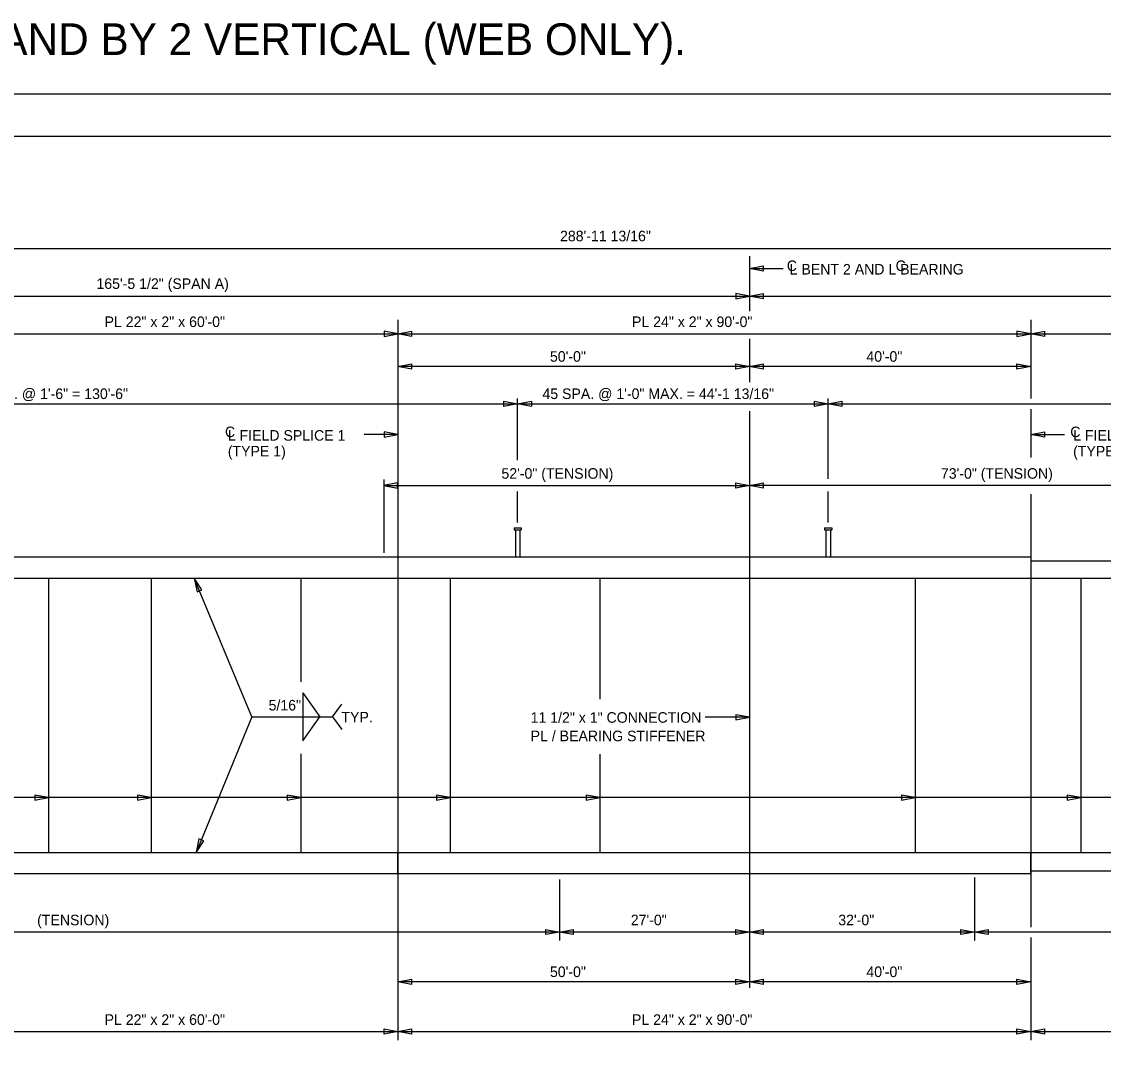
# Model space of a CAD drawing. Extents: x -383 to 7, y -330 to -94.
# Drawn here: x -255.6 to -204.4, y -145.2 to -96.1 of the extents above; entities that cross this region are included whole.
import ezdxf

# ---------------------------------------------------------------- set-up
doc = ezdxf.new("R2010")
doc.units = 0
for name, color, linetype in [('BR_AUTO DIMENSION', 7, 'Continuous'), ('BR_BORDER LINES', 7, 'Continuous'), ('BR_CENTER LINES', 7, 'Continuous'), ('BR_STRUCTURAL STEEL', 7, 'Continuous'), ('BR_TEXT', 7, 'Continuous'), ('Default', 7, 'Continuous'), ('Level 31', 7, 'Continuous')]:
    doc.layers.add(name, color=color, linetype=linetype)

msp = doc.modelspace()

# ---------------------------------------------------------------- linework, layer by layer
at = {"layer": 'BR_AUTO DIMENSION'}
for p, q in [((-276.288, -106.806), (-179.96, -106.806)), ((-221.135, -107.745), (-219.537, -107.745)), ((-276.288, -109.064), (-221.135, -109.064)), ((-221.135, -109.064), (-179.96, -109.064)), ((-257.802, -110.841), (-237.802, -110.841)), ((-237.802, -110.841), (-207.802, -110.841)), ((-207.802, -110.841), (-179.96, -110.841)), ((-221.135, -112.391), (-237.802, -112.391)), ((-207.802, -112.391), (-221.135, -112.391)), ((-274.622, -114.159), (-232.122, -114.159)), ((-232.122, -116.833), (-232.122, -113.909)), ((-232.122, -114.159), (-217.404, -114.159)), ((-217.404, -117.713), (-217.404, -113.909)), ((-217.404, -114.159), (-181.155, -114.159)), ((-237.802, -115.615), (-239.401, -115.615)), ((-207.802, -115.615), (-206.203, -115.615)), ((-238.469, -117.738), (-238.469, -121.213)), ((-238.469, -118.028), (-221.135, -118.028)), ((-232.122, -119.787), (-232.122, -118.317)), ((-196.802, -118.028), (-221.135, -118.028)), ((-217.404, -119.787), (-217.404, -118.317)), ((-244.714, -128.987), (-247.452, -122.412)), ((-242.299, -127.854), (-242.299, -130.121)), ((-242.299, -127.854), (-241.493, -128.987)), ((-240.89, -128.987), (-240.457, -128.38)), ((-244.714, -128.987), (-247.363, -135.412)), ((-244.714, -128.987), (-240.89, -128.987)), ((-242.299, -130.121), (-241.493, -128.987)), ((-240.89, -128.987), (-240.457, -129.595)), ((-221.135, -129.011), (-223.237, -129.011)), ((-185.75, -132.816), (-283.86, -132.816)), ((-230.135, -136.687), (-230.135, -139.586)), ((-210.469, -136.592), (-210.469, -139.586)), ((-230.135, -139.18), (-276.288, -139.18)), ((-221.135, -139.18), (-230.135, -139.18)), ((-210.469, -139.18), (-221.135, -139.18)), ((-179.96, -139.18), (-210.469, -139.18)), ((-221.135, -141.539), (-237.802, -141.539)), ((-207.802, -141.539), (-221.135, -141.539)), ((-257.802, -143.898), (-237.802, -143.898)), ((-237.802, -143.898), (-207.802, -143.898)), ((-207.802, -143.898), (-179.96, -143.898))]:
    msp.add_line(p, q, dxfattribs=at)
for points in [[(-220.485, -107.87), (-221.135, -107.745), (-220.485, -107.62)], [(-221.785, -109.189), (-221.135, -109.064), (-221.785, -108.939)], [(-220.485, -109.189), (-221.135, -109.064), (-220.485, -108.939)], [(-238.452, -110.966), (-237.802, -110.841), (-238.452, -110.716)], [(-237.152, -110.966), (-237.802, -110.841), (-237.152, -110.716)], [(-208.452, -110.966), (-207.802, -110.841), (-208.452, -110.716)], [(-207.152, -110.966), (-207.802, -110.841), (-207.152, -110.716)], [(-237.152, -112.516), (-237.802, -112.391), (-237.152, -112.266)], [(-221.785, -112.266), (-221.135, -112.391), (-221.785, -112.516)], [(-220.485, -112.516), (-221.135, -112.391), (-220.485, -112.266)], [(-208.452, -112.266), (-207.802, -112.391), (-208.452, -112.516)], [(-232.772, -114.034), (-232.122, -114.159), (-232.772, -114.284)], [(-231.472, -114.284), (-232.122, -114.159), (-231.472, -114.034)], [(-218.054, -114.034), (-217.404, -114.159), (-218.054, -114.284)], [(-216.754, -114.284), (-217.404, -114.159), (-216.754, -114.034)], [(-238.452, -115.74), (-237.802, -115.615), (-238.452, -115.49)], [(-207.152, -115.74), (-207.802, -115.615), (-207.152, -115.49)], [(-237.819, -117.903), (-238.469, -118.028), (-237.819, -118.153)], [(-221.785, -117.903), (-221.135, -118.028), (-221.785, -118.153)], [(-220.485, -118.153), (-221.135, -118.028), (-220.485, -117.903)], [(-247.087, -122.964), (-247.452, -122.412), (-247.317, -123.061)], [(-221.785, -129.136), (-221.135, -129.011), (-221.785, -128.886)], [(-255.007, -132.941), (-254.357, -132.816), (-255.007, -132.691)], [(-250.141, -132.941), (-249.491, -132.816), (-250.141, -132.691)], [(-243.052, -132.941), (-242.402, -132.816), (-243.052, -132.691)], [(-235.963, -132.941), (-235.313, -132.816), (-235.963, -132.691)], [(-228.874, -132.941), (-228.224, -132.816), (-228.874, -132.691)], [(-213.929, -132.941), (-213.279, -132.816), (-213.929, -132.691)], [(-206.072, -132.941), (-205.422, -132.816), (-206.072, -132.691)], [(-247.231, -134.764), (-247.363, -135.412), (-247, -134.859)], [(-230.785, -139.055), (-230.135, -139.18), (-230.785, -139.305)], [(-229.485, -139.305), (-230.135, -139.18), (-229.485, -139.055)], [(-221.785, -139.055), (-221.135, -139.18), (-221.785, -139.305)], [(-220.485, -139.305), (-221.135, -139.18), (-220.485, -139.055)], [(-211.119, -139.055), (-210.469, -139.18), (-211.119, -139.305)], [(-209.819, -139.305), (-210.469, -139.18), (-209.819, -139.055)], [(-237.152, -141.664), (-237.802, -141.539), (-237.152, -141.414)], [(-221.785, -141.414), (-221.135, -141.539), (-221.785, -141.664)], [(-220.485, -141.664), (-221.135, -141.539), (-220.485, -141.414)], [(-208.452, -141.414), (-207.802, -141.539), (-208.452, -141.664)], [(-238.452, -143.773), (-237.802, -143.898), (-238.452, -144.023)], [(-237.152, -144.023), (-237.802, -143.898), (-237.152, -143.773)], [(-208.452, -143.773), (-207.802, -143.898), (-208.452, -144.023)], [(-207.152, -144.023), (-207.802, -143.898), (-207.152, -143.773)]]:
    msp.add_lwpolyline(points, close=True, dxfattribs=at)
at = {"layer": 'BR_BORDER LINES'}
msp.add_line((-163.178, -101.489), (-297.843, -101.489), dxfattribs=at)
at = {"layer": 'BR_CENTER LINES'}
for p, q in [((-221.135, -107.17), (-221.135, -109.769)), ((-237.802, -110.184), (-237.802, -144.298)), ((-207.802, -110.184), (-207.802, -113.912)), ((-221.135, -111.078), (-221.135, -113.133)), ((-221.135, -114.504), (-221.135, -122.412)), ((-207.802, -114.419), (-207.802, -116.7)), ((-207.802, -118.447), (-207.802, -138.953)), ((-221.135, -135.412), (-221.135, -141.826)), ((-207.802, -139.444), (-207.802, -144.298))]:
    msp.add_line(p, q, dxfattribs=at)
at = {"layer": 'BR_STRUCTURAL STEEL'}
for p, q in [((-257.802, -121.412), (-237.802, -121.412)), ((-237.802, -121.412), (-237.802, -122.412)), ((-237.802, -121.412), (-207.802, -121.412)), ((-207.802, -121.412), (-207.802, -122.412)), ((-207.802, -121.6), (-179.96, -121.6)), ((-276.288, -122.412), (-179.96, -122.412)), ((-254.357, -122.412), (-254.357, -135.412)), ((-249.491, -122.412), (-249.491, -135.412)), ((-242.402, -122.412), (-242.402, -127.337)), ((-235.313, -122.412), (-235.313, -135.412)), ((-228.224, -122.412), (-228.224, -128.158)), ((-221.135, -122.412), (-221.135, -135.412)), ((-213.279, -122.412), (-213.279, -135.412)), ((-205.422, -122.412), (-205.422, -135.412)), ((-242.402, -130.739), (-242.402, -135.412)), ((-228.224, -130.754), (-228.224, -135.412)), ((-276.288, -135.412), (-179.96, -135.412)), ((-237.802, -136.412), (-237.802, -135.412)), ((-207.802, -136.412), (-207.802, -135.412)), ((-207.802, -136.287), (-179.96, -136.287)), ((-257.802, -136.412), (-237.802, -136.412)), ((-237.802, -136.412), (-207.802, -136.412))]:
    msp.add_line(p, q, dxfattribs=at)
at = {"layer": 'Default'}
for p, q in [((-232.294, -120.037), (-232.294, -120.131)), ((-232.294, -120.037), (-231.95, -120.037)), ((-232.294, -120.131), (-231.95, -120.131)), ((-232.231, -120.131), (-232.231, -121.412)), ((-232.012, -120.131), (-232.012, -121.412)), ((-231.95, -120.037), (-231.95, -120.131)), ((-217.576, -120.037), (-217.576, -120.131)), ((-217.576, -120.037), (-217.233, -120.037)), ((-217.576, -120.131), (-217.233, -120.131)), ((-217.514, -120.131), (-217.514, -121.412)), ((-217.295, -120.131), (-217.295, -121.412)), ((-217.233, -120.037), (-217.233, -120.131))]:
    msp.add_line(p, q, dxfattribs=at)
at = {"layer": 'Level 31'}
msp.add_lwpolyline([(-305.176, -187.489), (-161.176, -187.489), (-161.176, -99.489), (-305.176, -99.489)], close=True, dxfattribs=at)

# ---------------------------------------------------------------- texts
at = {"layer": 'BR_AUTO DIMENSION'}
for s, p in [('288\'-11 13/16"', (-230.112, -106.46)), ('165\'-5 1/2" (SPAN A)', (-252.087, -108.717)), ('PL 22" x 2" x 60\'-0"', (-251.701, -110.522)), ('PL 24" x 2" x 90\'-0"', (-226.701, -110.522)), ('50\'-0"', (-230.59, -112.166)), ('40\'-0"', (-215.59, -112.166)), ('87 SPA. @ 1\'-6" = 130\'-6"', (-258.263, -113.933)), ('45 SPA. @ 1\'-0" MAX. = 44\'-1 13/16"', (-230.946, -113.933)), (' 73\'-0" (TENSION)', (-212.243, -117.708)), ('5/16"', (-243.927, -128.687)), ('TYP.', (-240.473, -129.254)), ('(TENSION)', (-254.898, -138.86)), ('27\'-0"', (-226.757, -138.86)), ('50\'-0"', (-230.59, -141.314)), ('40\'-0"', (-215.59, -141.314)), ('PL 22" x 2" x 60\'-0"', (-251.701, -143.579)), ('PL 24" x 2" x 90\'-0"', (-226.701, -143.579))]:
    msp.add_text(s, height=0.5, rotation=360, dxfattribs=at).set_placement(p)
for s, p in [(' 52\'-0" (TENSION)', (-233.076, -117.708)), ('32\'-0"', (-216.923, -138.86))]:
    msp.add_text(s, height=0.5, dxfattribs=at).set_placement(p)
at = {"layer": 'BR_TEXT'}
msp.add_text('EXAGGERATED BY 6 VERTICAL (FLANGES ONLY) AND BY 2 VERTICAL (WEB ONLY).', height=1.5, dxfattribs=at).set_placement((-305.065, -97.636))
for s, p in [('C', (-219.363, -107.869)), ('L BENT 2 AND L BEARING', (-219.227, -108.035)), ('C', (-214.203, -107.869)), ('C', (-245.995, -115.739)), ('C', (-205.925, -115.739)), ('L FIELD SPLICE 1', (-245.86, -115.905)), ('L FIELD SPLICE 2', (-205.79, -115.905)), ('(TYPE 1)', (-245.86, -116.655)), ('(TYPE 2)', (-205.79, -116.655)), ('11 1/2" x 1" CONNECTION ', (-231.505, -129.268)), ('PL / BEARING STIFFENER', (-231.505, -130.143))]:
    msp.add_text(s, height=0.5, rotation=360, dxfattribs=at).set_placement(p)

doc.saveas('drawing.dxf')
